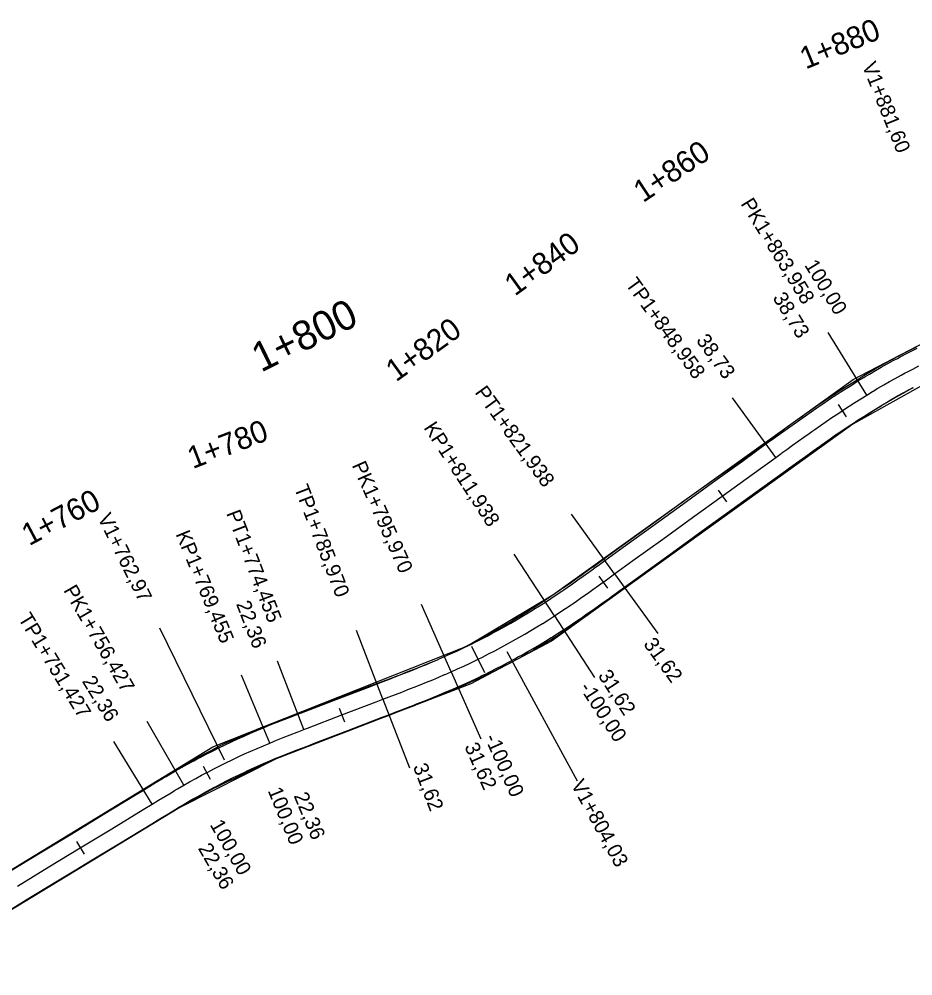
# Model space of a CAD drawing. Extents: x -636600 to -628587, y -1090963 to -1085869.
# Drawn here: x -633564.6 to -633443.1, y -1089312.8 to -1089182.6 of the extents above; entities that cross this region are included whole.
import ezdxf

# ---------------------------------------------------------------- set-up
doc = ezdxf.new("R2010")
doc.units = 0
for name, color, linetype in [('01_PARCELY_NÁVRH_PC', 7, 'Continuous'), ('HEKTOMETRY100', 7, 'Continuous'), ('HEKTOMETRY20', 7, 'Continuous'), ('HL_BODY', 7, 'Continuous'), ('POLOMERY', 7, 'Continuous'), ('situace_osa', 7, 'Continuous'), ('situace_těleso', 7, 'Continuous'), ('situace_vozovka', 7, 'Continuous'), ('VRCHOLY', 7, 'Continuous')]:
    doc.layers.add(name, color=color, linetype=linetype)

msp = doc.modelspace()

# ---------------------------------------------------------------- linework, layer by layer
at = {"layer": '01_PARCELY_NÁVRH_PC'}
for points in [[(-633575.45, -1089304.31), (-633538.21, -1089281.62), (-633503.71, -1089267.9), (-633492, -1089260.95), (-633451.18, -1089231.65), (-633438.04, -1089224.81), (-633425.38, -1089220.25), (-633408.84, -1089216.93), (-633404.02, -1089214.56), (-633384.22, -1089211.76), (-633378.02, -1089212.8), (-633366.96, -1089210.96)], [(-633363.15, -1089216.3), (-633403.15, -1089221.08), (-633422.37, -1089224.62), (-633437.28, -1089229.92), (-633451.21, -1089237.7), (-633492.18, -1089267.24), (-633503.13, -1089273.03), (-633529.6, -1089283.27), (-633542.71, -1089289.87), (-633580.4, -1089312.77)]]:
    msp.add_lwpolyline(points, dxfattribs=at)
at = {"layer": 'HEKTOMETRY100'}
msp.add_lwpolyline([(-633503.06, -1089267.91), (-633501.29, -1089271.5)], dxfattribs=at)
at = {"layer": 'HEKTOMETRY20'}
for points in [[(-633453.23, -1089235.06), (-633452.12, -1089236.73)], [(-633469.55, -1089246.69), (-633468.38, -1089248.31)], [(-633485.76, -1089258.41), (-633484.59, -1089260.03)], [(-633521.03, -1089276.35), (-633520.31, -1089278.22)], [(-633539.52, -1089284.23), (-633538.59, -1089286)], [(-633556.76, -1089294.5), (-633555.72, -1089296.2)]]:
    msp.add_lwpolyline(points, dxfattribs=at)
at = {"layer": 'HL_BODY'}
for points in [[(-633449.34, -1089233.76), (-633454.58, -1089225.25)], [(-633461.71, -1089242.25), (-633467.57, -1089234.14)], [(-633483.6, -1089258.08), (-633489.46, -1089249.98)], [(-633491.8, -1089263.81), (-633497.25, -1089255.42)], [(-633505.82, -1089271.41), (-633509.87, -1089262.26)], [(-633515.1, -1089275.14), (-633518.68, -1089265.81)], [(-633525.85, -1089279.27), (-633529.43, -1089269.94)], [(-633530.5, -1089281.1), (-633534.32, -1089271.86)], [(-633542.18, -1089286.84), (-633547.17, -1089278.18)], [(-633546.48, -1089289.41), (-633551.68, -1089280.87)]]:
    msp.add_lwpolyline(points, dxfattribs=at)
at = {"layer": 'POLOMERY'}
for points in [[(-633449.34, -1089233.76), (-633454.58, -1089225.25)], [(-633461.71, -1089242.25), (-633467.57, -1089234.14)], [(-633483.6, -1089258.08), (-633477.74, -1089266.19)], [(-633491.8, -1089263.81), (-633486.35, -1089272.19)], [(-633525.85, -1089279.27), (-633529.43, -1089269.94)], [(-633505.82, -1089271.41), (-633501.78, -1089280.55)], [(-633530.5, -1089281.1), (-633534.32, -1089271.86)], [(-633515.1, -1089275.14), (-633511.51, -1089284.48)], [(-633542.18, -1089286.84), (-633547.17, -1089278.18)], [(-633546.48, -1089289.41), (-633551.68, -1089280.87)]]:
    msp.add_lwpolyline(points, dxfattribs=at)
at = {"layer": 'situace_osa'}
msp.add_lwpolyline([(-633564.78, -1089300.55), (-633560.51, -1089297.95), (-633556.24, -1089295.35), (-633551.97, -1089292.75), (-633547.7, -1089290.15), (-633546.48, -1089289.41), (-633545.62, -1089288.89), (-633544.77, -1089288.37), (-633543.91, -1089287.86), (-633543.42, -1089287.56), (-633543.05, -1089287.35), (-633542.18, -1089286.84), (-633541.38, -1089286.38), (-633540.56, -1089285.93), (-633539.75, -1089285.49), (-633539.06, -1089285.12), (-633538.92, -1089285.05), (-633538.1, -1089284.62), (-633537.27, -1089284.2), (-633536.44, -1089283.78), (-633535.6, -1089283.38), (-633534.76, -1089282.98), (-633534.58, -1089282.89), (-633533.91, -1089282.59), (-633533.07, -1089282.2), (-633532.21, -1089281.83), (-633531.36, -1089281.46), (-633530.5, -1089281.1), (-633530, -1089280.9), (-633529.57, -1089280.73), (-633528.65, -1089280.36), (-633527.71, -1089279.99), (-633526.78, -1089279.63), (-633525.85, -1089279.27), (-633525.34, -1089279.08), (-633520.67, -1089277.28), (-633516, -1089275.49), (-633515.1, -1089275.14), (-633514.25, -1089274.82), (-633513.4, -1089274.49), (-633512.55, -1089274.16), (-633511.71, -1089273.83), (-633511.34, -1089273.69), (-633510.86, -1089273.5), (-633510.02, -1089273.16), (-633509.17, -1089272.82), (-633508.33, -1089272.48), (-633507.49, -1089272.13), (-633506.71, -1089271.79), (-633506.66, -1089271.77), (-633505.82, -1089271.41), (-633504.97, -1089271.02), (-633504.11, -1089270.63), (-633503.26, -1089270.23), (-633502.42, -1089269.82), (-633502.17, -1089269.7), (-633501.58, -1089269.41), (-633500.74, -1089268.98), (-633499.9, -1089268.55), (-633499.07, -1089268.11), (-633498.25, -1089267.66), (-633497.74, -1089267.38), (-633497.43, -1089267.21), (-633496.61, -1089266.74), (-633495.8, -1089266.27), (-633494.99, -1089265.8), (-633494.18, -1089265.31), (-633493.43, -1089264.85), (-633493.38, -1089264.82), (-633492.59, -1089264.32), (-633491.8, -1089263.81), (-633491.04, -1089263.31), (-633490.28, -1089262.81), (-633489.53, -1089262.29), (-633489.25, -1089262.11), (-633488.78, -1089261.78), (-633488.04, -1089261.26), (-633487.29, -1089260.74), (-633486.55, -1089260.21), (-633485.81, -1089259.68), (-633485.17, -1089259.22), (-633485.07, -1089259.15), (-633484.34, -1089258.62), (-633483.6, -1089258.08), (-633481.12, -1089256.29), (-633477.07, -1089253.36), (-633473.02, -1089250.43), (-633468.97, -1089247.5), (-633464.92, -1089244.57), (-633461.71, -1089242.25), (-633460.95, -1089241.7), (-633460.86, -1089241.64), (-633460.19, -1089241.15), (-633459.43, -1089240.6), (-633458.67, -1089240.05), (-633457.9, -1089239.51), (-633457.14, -1089238.97), (-633456.8, -1089238.73), (-633456.37, -1089238.43), (-633455.6, -1089237.89), (-633454.83, -1089237.36), (-633454.06, -1089236.83), (-633453.28, -1089236.3), (-633452.68, -1089235.9), (-633452.5, -1089235.78), (-633451.72, -1089235.27), (-633450.93, -1089234.76), (-633450.14, -1089234.26), (-633449.34, -1089233.76), (-633448.57, -1089233.3), (-633448.45, -1089233.22), (-633447.8, -1089232.83), (-633447.02, -1089232.38), (-633446.24, -1089231.93), (-633445.46, -1089231.49), (-633444.67, -1089231.06), (-633444.1, -1089230.76), (-633443.87, -1089230.63), (-633443.08, -1089230.22), (-633442.27, -1089229.8)], dxfattribs=at)
at = {"layer": 'situace_těleso'}
for points in [[(-633565.96, -1089298.6), (-633561.68, -1089296.03), (-633557.42, -1089293.4), (-633553.17, -1089290.78), (-633548.91, -1089288.15), (-633547.7, -1089287.4), (-633546.84, -1089286.88), (-633545.99, -1089286.35), (-633545.12, -1089285.83), (-633544.62, -1089285.53), (-633544.25, -1089285.3), (-633543.37, -1089284.79), (-633542.54, -1089284.31), (-633541.71, -1089283.85), (-633540.88, -1089283.39), (-633540.17, -1089283), (-633540.04, -1089282.93), (-633539.2, -1089282.48), (-633538.35, -1089282.05), (-633537.51, -1089281.59), (-633536.66, -1089281.17), (-633535.79, -1089280.78), (-633535.6, -1089280.7), (-633534.92, -1089280.39), (-633534.04, -1089280.01), (-633533.17, -1089279.64), (-633532.29, -1089279.27), (-633531.41, -1089278.91), (-633530.89, -1089278.7), (-633530.46, -1089278.53), (-633529.51, -1089278.16), (-633528.57, -1089277.8), (-633527.63, -1089277.44), (-633526.69, -1089277.08), (-633526.18, -1089276.89), (-633521.5, -1089275.12), (-633516.83, -1089273.34), (-633515.92, -1089273), (-633515.07, -1089272.68), (-633514.22, -1089272.36), (-633513.38, -1089272.03), (-633512.54, -1089271.71), (-633512.17, -1089271.57), (-633511.7, -1089271.38), (-633510.86, -1089271.06), (-633510.03, -1089270.73), (-633509.2, -1089270.39), (-633508.37, -1089270.05), (-633507.61, -1089269.72), (-633507.55, -1089269.7), (-633506.74, -1089269.34), (-633505.9, -1089268.96), (-633505.07, -1089268.57), (-633504.25, -1089268.16), (-633503.43, -1089267.75), (-633503.19, -1089267.63), (-633502.61, -1089267.33), (-633501.8, -1089266.9), (-633500.99, -1089266.47), (-633500.19, -1089266.02), (-633499.39, -1089265.57), (-633498.9, -1089265.29), (-633498.6, -1089265.11), (-633497.81, -1089264.65), (-633497.03, -1089264.17), (-633496.25, -1089263.69), (-633495.47, -1089263.2), (-633494.75, -1089262.74), (-633494.7, -1089262.71), (-633493.92, -1089262.22), (-633493.16, -1089261.72), (-633492.42, -1089261.23), (-633491.68, -1089260.73), (-633490.94, -1089260.23), (-633490.67, -1089260.04), (-633490.21, -1089259.72), (-633489.47, -1089259.21), (-633488.74, -1089258.69), (-633488.01, -1089258.17), (-633487.28, -1089257.64), (-633486.64, -1089257.18), (-633486.54, -1089257.11), (-633485.81, -1089256.58), (-633485.07, -1089256.05), (-633482.59, -1089254.25), (-633478.54, -1089251.32), (-633474.5, -1089248.39), (-633470.43, -1089245.48), (-633466.33, -1089242.61), (-633463.15, -1089240.26), (-633462.39, -1089239.71), (-633462.3, -1089239.65), (-633461.63, -1089239.16), (-633460.86, -1089238.61), (-633460.1, -1089238.05), (-633459.33, -1089237.5), (-633458.56, -1089236.96), (-633458.22, -1089236.71), (-633457.79, -1089236.41), (-633457.01, -1089235.86), (-633456.23, -1089235.32), (-633455.45, -1089234.79), (-633454.66, -1089234.25), (-633454.04, -1089233.84), (-633453.87, -1089233.72), (-633453.07, -1089233.2), (-633452.26, -1089232.68), (-633451.45, -1089232.17), (-633450.63, -1089231.67), (-633449.84, -1089231.19), (-633449.72, -1089231.12), (-633449.05, -1089230.71), (-633448.27, -1089230.23), (-633447.47, -1089229.77), (-633446.66, -1089229.32), (-633445.85, -1089228.88), (-633445.27, -1089228.58), (-633445.03, -1089228.45), (-633444.21, -1089228.03), (-633443.39, -1089227.61), (-633442.56, -1089227.2)], [(-633443.03, -1089232.77), (-633443.57, -1089233.07), (-633444.34, -1089233.5), (-633445.11, -1089233.93), (-633445.87, -1089234.37), (-633446.63, -1089234.82), (-633447.26, -1089235.2), (-633447.38, -1089235.27), (-633448.13, -1089235.74), (-633448.91, -1089236.22), (-633449.68, -1089236.72), (-633450.45, -1089237.22), (-633451.23, -1089237.71), (-633451.4, -1089237.82), (-633452.01, -1089238.2), (-633452.78, -1089238.7), (-633453.56, -1089239.21), (-633454.31, -1089239.75), (-633455.06, -1089240.3), (-633455.47, -1089240.6), (-633455.81, -1089240.85), (-633456.56, -1089241.4), (-633457.3, -1089241.96), (-633458.05, -1089242.52), (-633458.8, -1089243.08), (-633459.46, -1089243.57), (-633459.55, -1089243.64), (-633460.3, -1089244.2), (-633463.48, -1089246.55), (-633467.62, -1089249.36), (-633471.69, -1089252.27), (-633475.71, -1089255.23), (-633479.74, -1089258.19), (-633482.21, -1089260.01), (-633482.94, -1089260.55), (-633483.68, -1089261.09), (-633483.77, -1089261.16), (-633484.41, -1089261.63), (-633485.16, -1089262.17), (-633485.9, -1089262.7), (-633486.65, -1089263.24), (-633487.4, -1089263.78), (-633487.88, -1089264.11), (-633488.16, -1089264.31), (-633488.92, -1089264.83), (-633489.68, -1089265.35), (-633490.46, -1089265.87), (-633491.25, -1089266.42), (-633492.06, -1089266.94), (-633492.11, -1089266.97), (-633492.88, -1089267.44), (-633493.71, -1089267.93), (-633494.54, -1089268.42), (-633495.38, -1089268.89), (-633496.22, -1089269.36), (-633496.54, -1089269.54), (-633497.06, -1089269.82), (-633497.91, -1089270.27), (-633498.77, -1089270.71), (-633499.63, -1089271.15), (-633500.49, -1089271.57), (-633501.11, -1089271.87), (-633501.36, -1089271.99), (-633502.23, -1089272.39), (-633503.11, -1089272.79), (-633503.99, -1089273.18), (-633504.87, -1089273.56), (-633505.73, -1089273.92), (-633505.79, -1089273.94), (-633506.58, -1089274.28), (-633507.44, -1089274.64), (-633508.29, -1089274.99), (-633509.14, -1089275.34), (-633510, -1089275.68), (-633510.48, -1089275.87), (-633510.85, -1089276.02), (-633511.7, -1089276.35), (-633512.56, -1089276.68), (-633513.41, -1089277.01), (-633514.26, -1089277.34), (-633515.16, -1089277.68), (-633519.83, -1089279.48), (-633524.5, -1089281.27), (-633525.01, -1089281.46), (-633525.94, -1089281.82), (-633526.86, -1089282.18), (-633527.79, -1089282.54), (-633528.7, -1089282.9), (-633529.11, -1089283.07), (-633529.6, -1089283.27), (-633530.44, -1089283.63), (-633531.27, -1089284), (-633532.1, -1089284.37), (-633532.92, -1089284.76), (-633533.57, -1089285.07), (-633533.74, -1089285.15), (-633534.55, -1089285.56), (-633535.36, -1089285.97), (-633536.19, -1089286.35), (-633537.01, -1089286.74), (-633537.83, -1089287.14), (-633537.96, -1089287.2), (-633538.63, -1089287.56), (-633539.43, -1089287.99), (-633540.22, -1089288.44), (-633541.01, -1089288.89), (-633541.86, -1089289.37), (-633542.22, -1089289.58), (-633542.71, -1089289.87), (-633543.56, -1089290.37), (-633544.41, -1089290.88), (-633545.27, -1089291.39), (-633546.49, -1089292.13), (-633550.77, -1089294.71), (-633555.06, -1089297.29), (-633559.34, -1089299.88), (-633563.6, -1089302.49), (-633567.86, -1089305.11)]]:
    msp.add_lwpolyline(points, dxfattribs=at)
at = {"layer": 'situace_vozovka'}
for points in [[(-633565.95, -1089298.63), (-633561.68, -1089296.03), (-633557.41, -1089293.43), (-633553.14, -1089290.83), (-633548.87, -1089288.23), (-633547.65, -1089287.49), (-633546.79, -1089286.97), (-633545.93, -1089286.44), (-633545.06, -1089285.92), (-633544.56, -1089285.63), (-633544.19, -1089285.41), (-633543.31, -1089284.89), (-633542.48, -1089284.42), (-633541.65, -1089283.96), (-633540.81, -1089283.51), (-633540.11, -1089283.13), (-633539.97, -1089283.06), (-633539.13, -1089282.62), (-633538.28, -1089282.19), (-633537.43, -1089281.76), (-633536.57, -1089281.35), (-633535.71, -1089280.94), (-633535.53, -1089280.86), (-633534.85, -1089280.54), (-633533.98, -1089280.15), (-633533.11, -1089279.77), (-633532.24, -1089279.39), (-633531.36, -1089279.02), (-633530.84, -1089278.81), (-633530.41, -1089278.64), (-633529.47, -1089278.26), (-633528.53, -1089277.89), (-633527.59, -1089277.53), (-633526.65, -1089277.17), (-633526.15, -1089276.98), (-633521.48, -1089275.18), (-633516.81, -1089273.39), (-633515.9, -1089273.04), (-633515.06, -1089272.72), (-633514.21, -1089272.39), (-633513.37, -1089272.07), (-633512.53, -1089271.74), (-633512.16, -1089271.6), (-633511.69, -1089271.41), (-633510.85, -1089271.08), (-633510.02, -1089270.74), (-633509.19, -1089270.4), (-633508.37, -1089270.05), (-633507.6, -1089269.73), (-633507.55, -1089269.7), (-633506.73, -1089269.35), (-633505.9, -1089268.97), (-633505.06, -1089268.59), (-633504.23, -1089268.2), (-633503.4, -1089267.8), (-633503.17, -1089267.68), (-633502.58, -1089267.39), (-633501.76, -1089266.98), (-633500.95, -1089266.56), (-633500.14, -1089266.13), (-633499.33, -1089265.69), (-633498.83, -1089265.42), (-633498.53, -1089265.24), (-633497.73, -1089264.79), (-633496.93, -1089264.33), (-633496.14, -1089263.86), (-633495.36, -1089263.39), (-633494.62, -1089262.94), (-633494.57, -1089262.91), (-633493.8, -1089262.42), (-633493.02, -1089261.92), (-633492.28, -1089261.43), (-633491.54, -1089260.94), (-633490.8, -1089260.44), (-633490.53, -1089260.25), (-633490.06, -1089259.93), (-633489.33, -1089259.42), (-633488.59, -1089258.9), (-633487.86, -1089258.38), (-633487.12, -1089257.85), (-633486.49, -1089257.39), (-633486.39, -1089257.32), (-633485.66, -1089256.79), (-633484.92, -1089256.26), (-633482.44, -1089254.47), (-633478.39, -1089251.54), (-633474.34, -1089248.61), (-633470.29, -1089245.67), (-633466.23, -1089242.74), (-633463.03, -1089240.42), (-633462.27, -1089239.87), (-633462.18, -1089239.81), (-633461.51, -1089239.32), (-633460.74, -1089238.77), (-633459.98, -1089238.22), (-633459.21, -1089237.68), (-633458.44, -1089237.13), (-633458.1, -1089236.89), (-633457.67, -1089236.58), (-633456.89, -1089236.04), (-633456.11, -1089235.5), (-633455.32, -1089234.97), (-633454.54, -1089234.43), (-633453.92, -1089234.02), (-633453.74, -1089233.91), (-633452.95, -1089233.38), (-633452.14, -1089232.86), (-633451.33, -1089232.35), (-633450.52, -1089231.85), (-633449.73, -1089231.37), (-633449.61, -1089231.29), (-633448.94, -1089230.9), (-633448.15, -1089230.43), (-633447.35, -1089229.98), (-633446.55, -1089229.53), (-633445.74, -1089229.08), (-633445.16, -1089228.77), (-633444.93, -1089228.65), (-633444.11, -1089228.22), (-633443.29, -1089227.8), (-633442.47, -1089227.38)], [(-633567.88, -1089305.07), (-633563.61, -1089302.47), (-633559.34, -1089299.87), (-633555.07, -1089297.27), (-633550.8, -1089294.67), (-633546.53, -1089292.07), (-633545.31, -1089291.33), (-633544.45, -1089290.81), (-633543.6, -1089290.3), (-633542.76, -1089289.79), (-633542.27, -1089289.5), (-633541.91, -1089289.29), (-633541.06, -1089288.79), (-633540.27, -1089288.35), (-633539.48, -1089287.9), (-633538.68, -1089287.47), (-633538, -1089287.11), (-633537.88, -1089287.04), (-633537.07, -1089286.62), (-633536.26, -1089286.21), (-633535.44, -1089285.8), (-633534.63, -1089285.41), (-633533.8, -1089285.02), (-633533.63, -1089284.93), (-633532.98, -1089284.63), (-633532.15, -1089284.26), (-633531.32, -1089283.89), (-633530.48, -1089283.53), (-633529.64, -1089283.18), (-633529.15, -1089282.98), (-633528.73, -1089282.81), (-633527.82, -1089282.45), (-633526.9, -1089282.09), (-633525.97, -1089281.73), (-633525.04, -1089281.37), (-633524.53, -1089281.18), (-633519.86, -1089279.39), (-633515.2, -1089277.59), (-633514.29, -1089277.25), (-633513.44, -1089276.92), (-633512.59, -1089276.59), (-633511.74, -1089276.26), (-633510.89, -1089275.93), (-633510.52, -1089275.78), (-633510.03, -1089275.59), (-633509.18, -1089275.25), (-633508.32, -1089274.91), (-633507.47, -1089274.56), (-633506.62, -1089274.2), (-633505.82, -1089273.86), (-633505.76, -1089273.84), (-633504.91, -1089273.46), (-633504.04, -1089273.07), (-633503.16, -1089272.67), (-633502.3, -1089272.26), (-633501.43, -1089271.84), (-633501.18, -1089271.72), (-633500.57, -1089271.42), (-633499.71, -1089270.98), (-633498.86, -1089270.54), (-633498.01, -1089270.09), (-633497.17, -1089269.64), (-633496.65, -1089269.35), (-633496.33, -1089269.17), (-633495.49, -1089268.7), (-633494.66, -1089268.22), (-633493.83, -1089267.73), (-633493.01, -1089267.23), (-633492.24, -1089266.76), (-633492.19, -1089266.73), (-633491.38, -1089266.21), (-633490.57, -1089265.7), (-633489.8, -1089265.19), (-633489.03, -1089264.67), (-633488.26, -1089264.15), (-633487.98, -1089263.96), (-633487.5, -1089263.63), (-633486.74, -1089263.1), (-633485.99, -1089262.57), (-633485.25, -1089262.04), (-633484.5, -1089261.51), (-633483.86, -1089261.04), (-633483.76, -1089260.97), (-633483.02, -1089260.44), (-633482.28, -1089259.91), (-633479.8, -1089258.11), (-633475.75, -1089255.18), (-633471.7, -1089252.25), (-633467.65, -1089249.32), (-633463.6, -1089246.39), (-633460.39, -1089244.07), (-633459.63, -1089243.52), (-633459.55, -1089243.46), (-633458.87, -1089242.97), (-633458.11, -1089242.43), (-633457.36, -1089241.88), (-633456.6, -1089241.34), (-633455.84, -1089240.8), (-633455.5, -1089240.56), (-633455.08, -1089240.27), (-633454.32, -1089239.74), (-633453.56, -1089239.21), (-633452.8, -1089238.69), (-633452.03, -1089238.17), (-633451.43, -1089237.77), (-633451.26, -1089237.66), (-633450.49, -1089237.15), (-633449.72, -1089236.66), (-633448.94, -1089236.16), (-633448.16, -1089235.68), (-633447.41, -1089235.22), (-633447.29, -1089235.15), (-633446.66, -1089234.77), (-633445.9, -1089234.33), (-633445.13, -1089233.89), (-633444.36, -1089233.46), (-633443.59, -1089233.04), (-633443.04, -1089232.74)]]:
    msp.add_lwpolyline(points, dxfattribs=at)
at = {"layer": 'VRCHOLY'}
for points in [[(-633536.62, -1089283.41), (-633545.44, -1089265.46)], [(-633498.24, -1089268.67), (-633488.71, -1089286.26)]]:
    msp.add_lwpolyline(points, dxfattribs=at)

# ---------------------------------------------------------------- texts
at = {"layer": 'HEKTOMETRY100'}
msp.add_text('1+800', height=4, rotation=26.1774, dxfattribs=at).set_placement((-633531.67, -1089230.72))
at = {"layer": 'HEKTOMETRY20'}
for s, rotation, p in [('1+880', 22.3934, (-633457.64, -1089189.49)), ('1+860', 33.5534, (-633479.75, -1089207.66)), ('1+840', 35.8821, (-633497.17, -1089220.38)), ('1+820', 35.7745, (-633513.32, -1089232.05)), ('1+780', 21.0038, (-633540.96, -1089243.84)), ('1+760', 27.8532, (-633563.19, -1089254.33))]:
    msp.add_text(s, height=3, rotation=rotation, dxfattribs=at).set_placement(p)
at = {"layer": 'HL_BODY'}
for s, rotation, p in [('PK1+863,958', 301.5849, (-633466.53, -1089207.73)), ('TP1+848,958', 305.8821, (-633482.21, -1089218.69)), ('PT1+821,938', 305.8821, (-633502.69, -1089233.41)), ('KP1+811,938', 303.0173, (-633509.63, -1089238.21)), ('PK1+795,970', 293.8686, (-633519.36, -1089243.3)), ('TP1+785,970', 291.0038, (-633527.21, -1089246.39)), ('PT1+774,455', 291.0038, (-633536.44, -1089249.84)), ('KP1+769,455', 292.4362, (-633543.32, -1089252.67)), ('PK1+756,427', 299.9004, (-633558.59, -1089260.31)), ('TP1+751,427', 301.3328, (-633564.75, -1089264.15))]:
    msp.add_text(s, height=2, rotation=rotation, dxfattribs=at).set_placement(p)
at = {"layer": 'POLOMERY'}
for s, rotation, p in [('100,00', 301.5849, (-633457.86, -1089216.08)), ('38,73', 301.5849, (-633462.18, -1089220.53)), ('38,73', 305.8821, (-633472.6, -1089226.34)), ('22,36', 291.0038, (-633535.09, -1089262.17)), ('31,62', 305.8821, (-633479.77, -1089267.65)), ('31,62', 303.0173, (-633485.93, -1089271.92)), ('22,36', 301.3328, (-633556.07, -1089272.68)), ('-100,00', 303.0173, (-633488.45, -1089273.56)), ('-100,00', 293.8686, (-633501.32, -1089280.35)), ('31,62', 293.8686, (-633504.06, -1089281.56)), ('31,62', 291.0038, (-633511.05, -1089284.3)), ('100,00', 292.4362, (-633530.79, -1089287.57)), ('22,36', 292.4362, (-633527.26, -1089288.26)), ('100,00', 299.9004, (-633538.68, -1089292.2)), ('22,36', 299.9004, (-633540.29, -1089295.42))]:
    msp.add_text(s, height=2, rotation=rotation, dxfattribs=at).set_placement(p)
at = {"layer": 'VRCHOLY'}
for s, rotation, p in [('V1+881,60', 291.782, (-633450, -1089188.93)), ('V1+762,97', 296.1683, (-633553.93, -1089250.45)), ('V1+804,03', 298.4429, (-633489.59, -1089286.73))]:
    msp.add_text(s, height=2, rotation=rotation, dxfattribs=at).set_placement(p)

doc.saveas('drawing.dxf')
